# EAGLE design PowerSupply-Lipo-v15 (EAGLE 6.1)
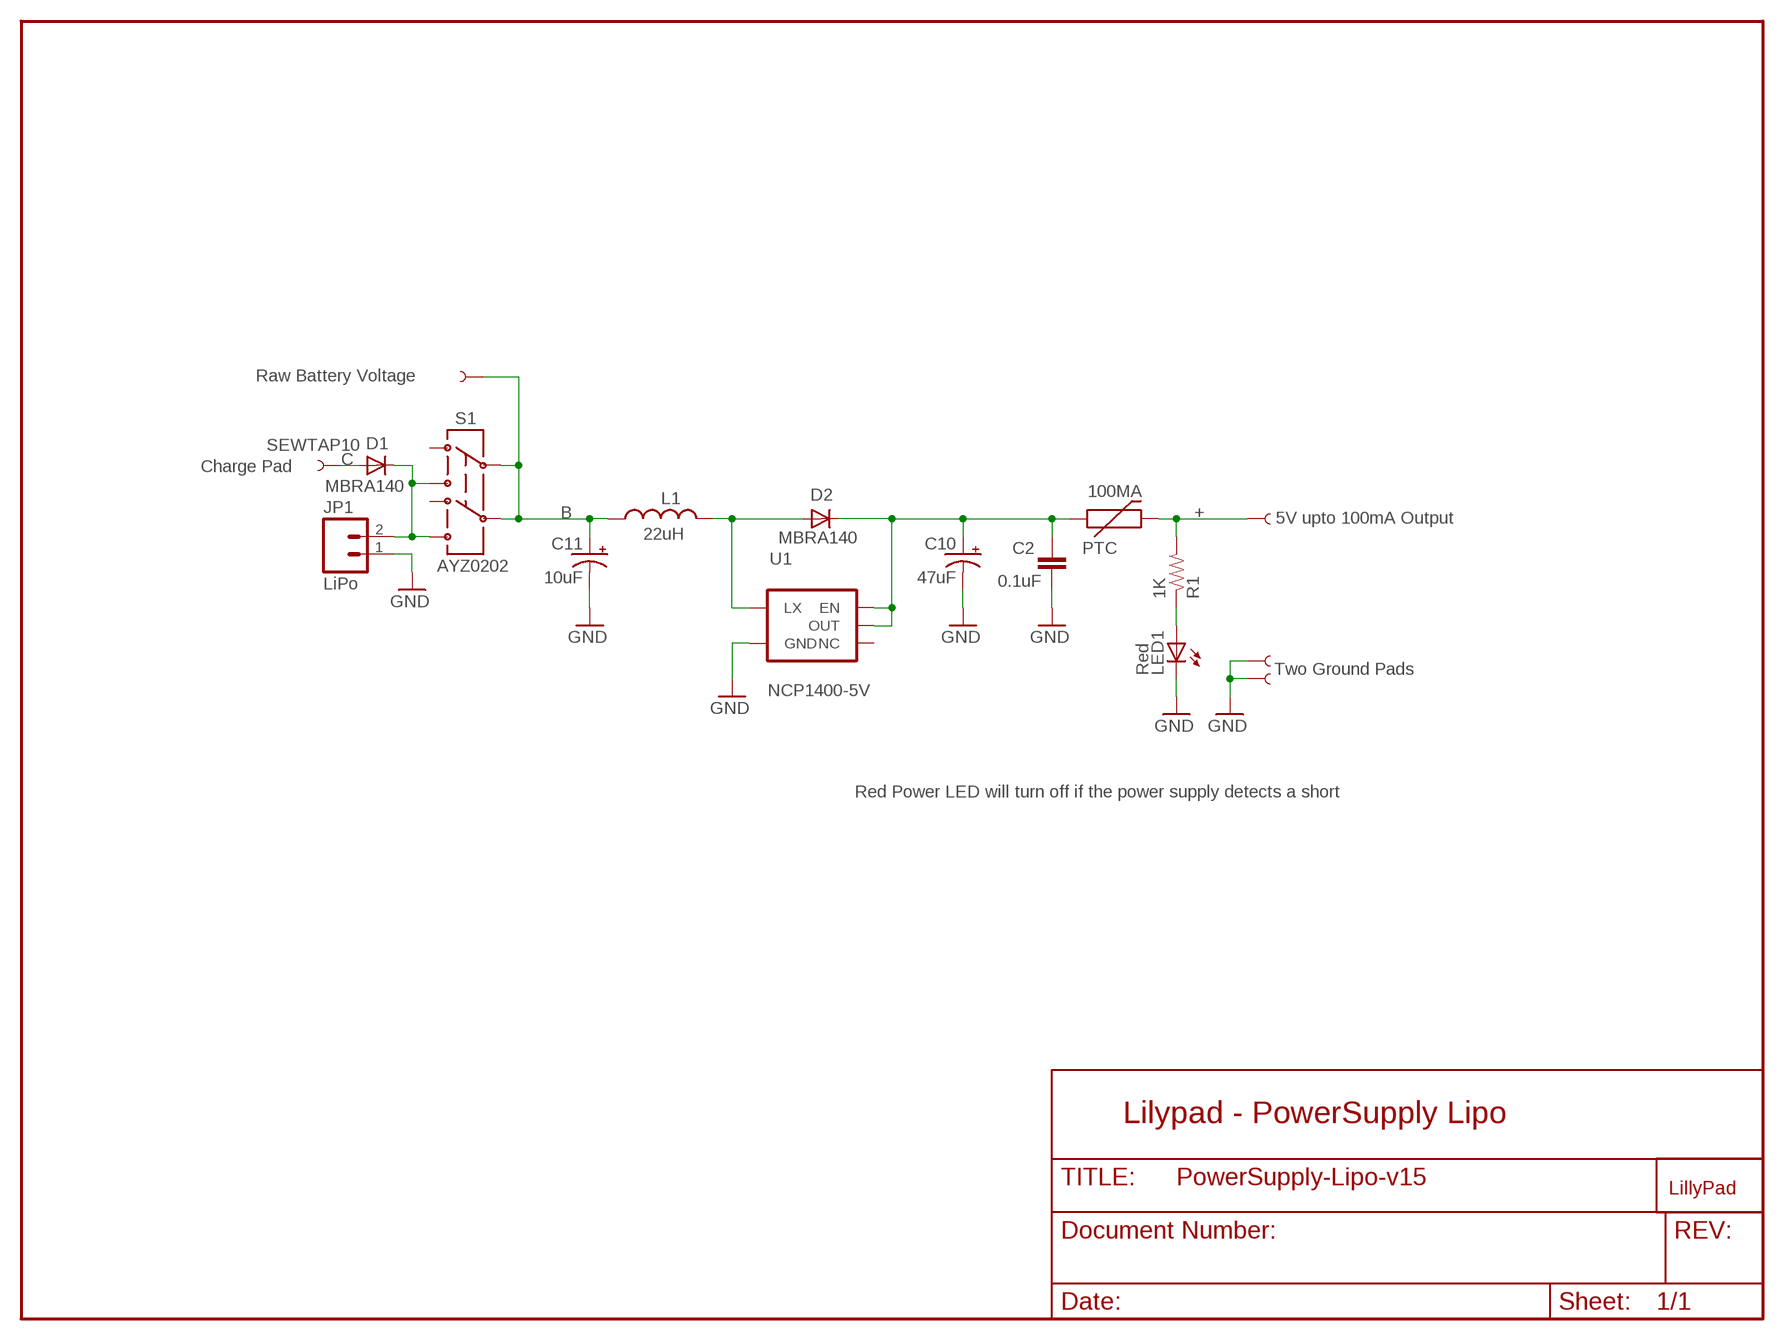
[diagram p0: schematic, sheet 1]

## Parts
100MA  PTC  PTCSMD  [PTC-1206]
C2  0.1uF  CAP0603-CAP  [0603-CAP]
C10  47uF  CAP_POL2  [EIA3528-21]
C11  10uF  CAP_POL1206  [CPOL_1206]
D1  MBRA140  DIODESMA  [SMA-DIODE]
D2  MBRA140  DIODESMA  [SMA-DIODE]
JP1  LiPo  M02-JST-2MM-SMT  [JST-2-SMD]
L1  22uH  INDUCTORCR54  [CR54]
LED1  Red  LED1206  [LED-1206]
R1  1K  RESISTOR0603-RES  [0603-RES]
S1  AYZ0202  [AYZ0202]
U1  NCP1400-5V  V_REG_NCP1400SOT23-5  [SOT23-5]
U$1  SEWTAP10  [PETAL-LONG-2-2SIDE]
U$2  SEWTAP10  [PETAL-LONG-2-2SIDE]
U$3  SEWTAP10  [PETAL-LONG-2-2SIDE]
U$4  SEWTAP10  [PETAL-LONG-2-2SIDE]
U$5  SEWTAP10  [PETAL-LONG-2-2SIDE]
U$7  LOGO-LPLP  [LOGO-LILYPAD]

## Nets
+: 100MA.2 R1.2 U$1.1
B: C11.A(+) L1.P$2 S1.2 S1.5 U$3.1
C: D1.A U$2.1
GND: C2.2 C10.C(-) C11.C(-) JP1.1 LED1.C U1.4(GND) U$4.1 U$5.1
N$1: LED1.A R1.1
N$2: 100MA.1 C2.1 C10.A(+) D2.C U1.1(EN) U1.2(OUT)
N$5: D1.C JP1.2 S1.1 S1.4
N$16: D2.A L1.P$1 U1.5(LX)
Unconnected: S1.3 S1.6 U1.3(NC)

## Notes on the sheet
- Raw Battery Voltage
- Charge Pad
- 5V upto 100mA Output
- Two Ground Pads
- Red Power LED will turn off if the power supply detects a short
- Lilypad - PowerSupply Lipo

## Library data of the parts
100MA = SparkFun:PTC: Resettable Fuse PTC
C2 = SparkFun:CAP: Capacitor
C10 C11 = SparkFun-Nate:CAP_POL
D1 D2 = SparkFun-Nate:DIODE
JP1 = SparkFun:M02: Header 2
L1 = SparkFun-Nate:INDUCTOR: Basic Inductor/Choke - 0603 and 1206
LED1 = SparkFun:LED: LEDs
R1 = SparkFun:RESISTOR: Resistor
S1 = SparkFun:AYZ0202: SPDT Slide Switch Simple SMD single-pull double-throw slide switch. Good for less than 350mA power switch, switching UARTs between devices, etc. Spark Fun Electronics SKU : COM-00597
U1 = SparkFun:V_REG_NCP1400: Switching step-up voltage regulator NCP1400 switiching regulator takes single cell AA and outputs 100mA at 3.3V or 5V with minimal number of external components.
U$1-U$5 = LilyPad-Wearables:SEWTAP
U$7 = LilyPad-Wearables:LOGO-LP

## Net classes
0 Default: width 0.203 mm
1 Power: width 0.305 mm
3 ButtonSignal: width 0.203 mm

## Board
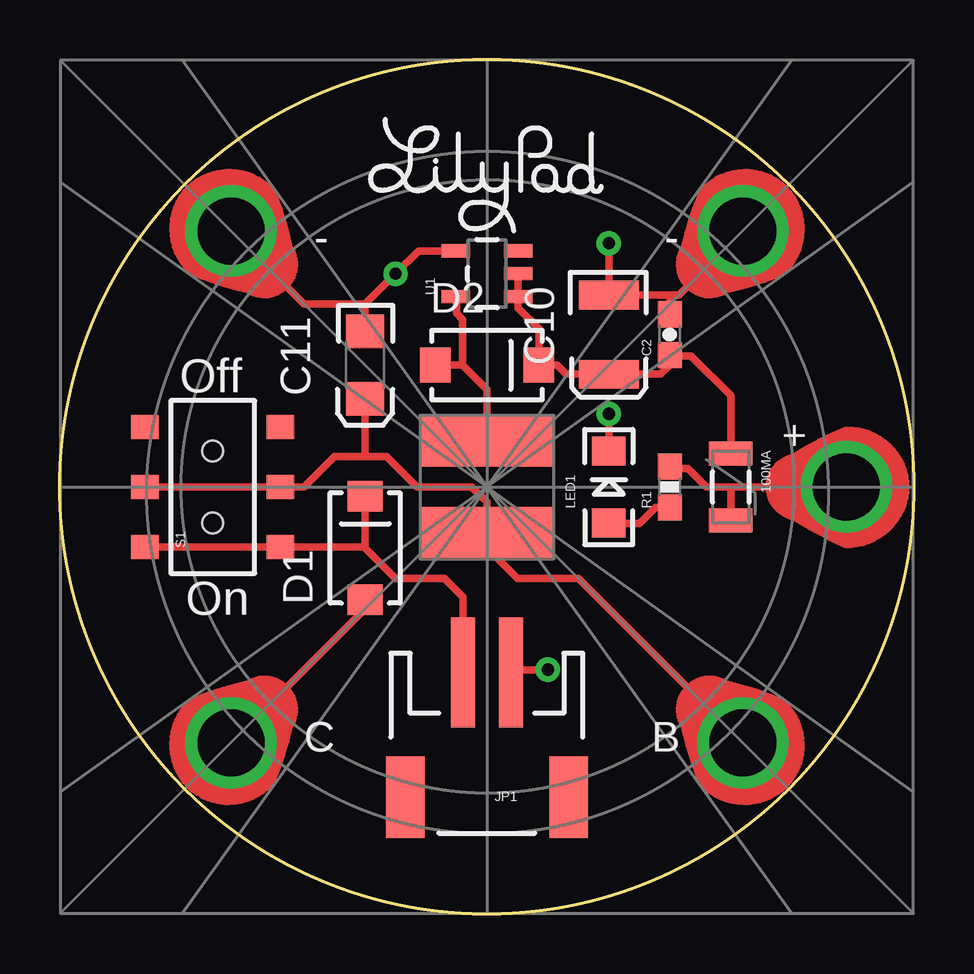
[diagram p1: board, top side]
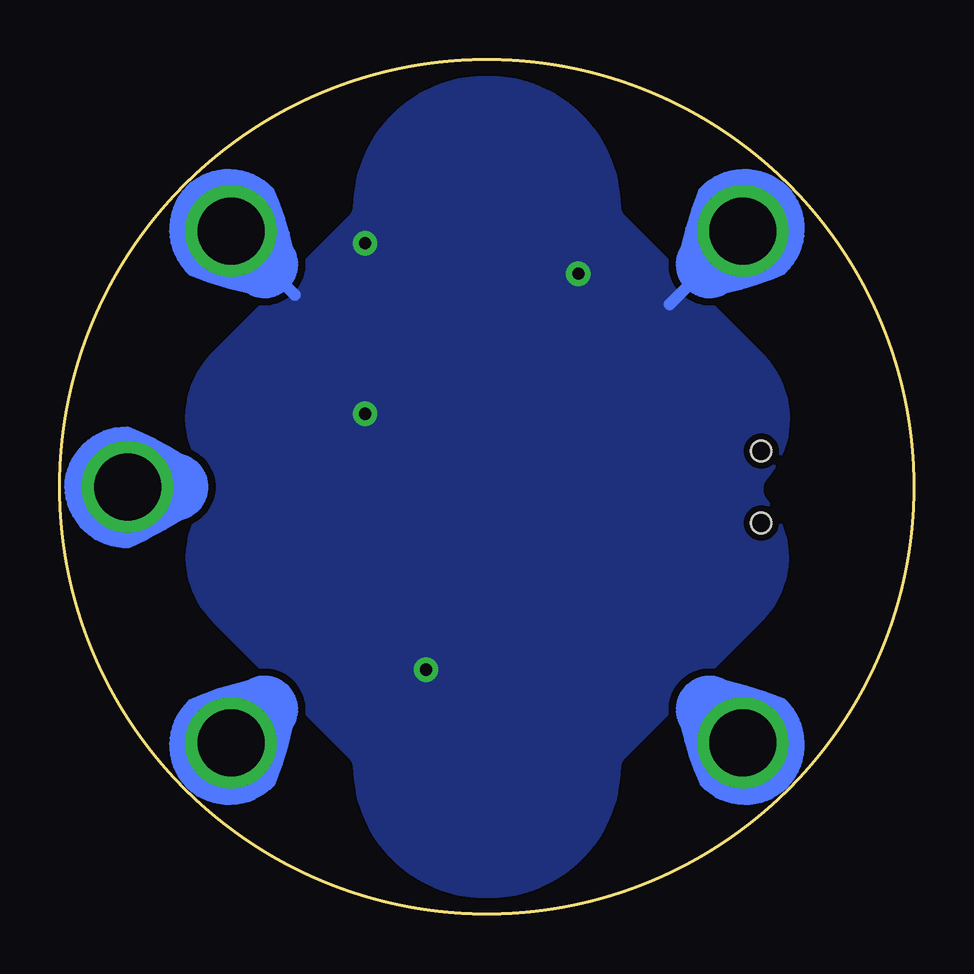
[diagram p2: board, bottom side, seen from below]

Size 35.6 x 35.6 mm. Coordinates in mm from the lower left corner, seen from the top.
Outline: circle at 17.8,17.8 radius 17.8
Copper layers (1*16): Top 0.035mm / dielectric 1.5mm / Bottom 0.035mm
Design rules "SparkFun": minimum track width 8mil, minimum drill 20mil, track to track 8mil, track to pad 8mil, pad to pad 8mil, via to via 8mil, smd to smd 8mil, copper to edge 10mil, drill to drill 8mil, minimum pad ring 12mil, minimum via ring 10mil, stop-mask expansion 4mil, vias tented up to drill 20mil, thermal gap 10mil
bRestrict: area 0,0 to 35.6,35.6

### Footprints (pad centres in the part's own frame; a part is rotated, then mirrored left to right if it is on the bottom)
PTC-1206 = smd 1 x 1.8: 1 -1.4,0; 2 1.4,0
0603-CAP = smd 1.1 x 1: 1 -0.85,0; 2 0.85,0
EIA3528-21 = smd 2.5 x 1.2: A 0,-1.65; C 0,1.65
CPOL_1206 = smd 1.6 x 1.4: A 0,-1.4; C 0,1.4
SMA-DIODE = smd 1.27 x 1.47: A -2.15,0; C 2.15,0
JST-2-SMD = smd 1 x 4.6: 1 -1,-3.7; 2 1,-3.7 | smd 1.6 x 3.4: NC1 -3.4,1.5; NC2 3.4,1.5
CR54 = smd 5.5 x 2.15: P$1 0,1.92; P$2 0,-1.92
LED-1206 = smd 1.2 x 1.4: A -1.5,0; C 1.5,0
0603-RES = smd 1.1 x 1: 1 -0.85,0; 2 0.85,0
AYZ0202 = smd 1 x 1.15: 1 -2.5,2.825; 2 0,2.825; 3 2.5,2.825; 4 -2.5,-2.825; 5 0,-2.825; 6 2.5,-2.825 | hole 0.85: 1.5,0; -1.5,0
SOT23-5 = smd 0.55 x 1.2: 1 -0.95,-1.3; 2 0,-1.3; 3 0.95,-1.3; 4 0.95,1.3; 5 -0.95,1.3
PETAL-LONG-2-2SIDE = drill 2.794 round: 1 0,0

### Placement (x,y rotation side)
100MA  27.96,17.8 270 top
C2  25.42,24.15 90 top
C10  22.88,24.15 0 top
C11  12.72,22.88 0 top
D1  12.72,15.26 90 top
D2  17.8,22.88 0 top
JP1  17.8,6.37 180 top
L1  17.8,17.8 0 top
LED1  22.88,17.8 90 top
R1  25.42,17.8 90 top
S1  6.37,17.8 90 top
U1  17.8,26.69 90 top
U$1  32.79,17.8 90 top
U$2  7.13,7.13 315 top
U$3  28.47,7.13 45 top
U$4  28.47,28.47 135 top
U$5  7.13,28.47 225 top
U$7  17.8,31.13 0 top

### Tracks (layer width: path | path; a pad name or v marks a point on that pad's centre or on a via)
+
  Top 0.305: 27.96,17.8 26.94,17.8 26.18,18.56 25.55,18.56 25.46,18.65 R1.2 | 27.96,17.8 U$1.1 | 27.96,17.8 100MA.2
B
  Top 0.305: 17.8,16.4 17.8,15.89 | 17.8,16.4 17.8,16.53 | 12.72,19.07 C11.A | 18.05,16.28 L1.P$2 17.8,15.89 | S1.2 S1.5 10.18,17.8 11.45,19.07 12.72,19.07 | 12.72,19.07 13.61,19.07 14.88,17.8 17.16,17.8 17.8,17.16 17.8,16.4 | U$3.1 21.61,13.99 19.07,13.99 17.8,15.26 17.8,15.89
C
  Top 0.305: D1.A 12.72,12.72 U$2.1
GND  (via drill 0.51)
  Top 0.305: C2.2 25.42,25.8 | 25.42,25.8 25.29,25.8 C10.C v22.88,27.96 | LED1.C v22.88,20.85 | 18.82,10.43 JP1.1 18.91,10.18 v20.34,10.18 | 12.72,24.15 C11.C 12.72,25.42 | U1.4 14.94,27.64 v13.99,26.69 12.72,25.42 | 12.72,25.42 10.18,25.42 8.91,26.69 | U$4.1 25.8,25.8 25.42,25.8
  Bottom 0.508: U$5.1 10.18,25.42 | U$4.1 25.8,25.8
  pour Bottom (isolate 0.305): 35.58,0.02 0.02,0.02 -0.23,15.26 -0.23,20.59 0.02,35.58 35.58,35.58
N$1
  Top 0.305: R1.1 24.82,16.95 24.15,16.28 22.88,16.28 LED1.A
N$2
  Top 0.305: U1.2 19.1,25.83 19.07,25.8 19.1,25.77 U1.1 19.1,25.26 19.96,24.4 D2.C 20.72,22.88 21.1,22.5 C10.A 25.04,22.5 25.42,22.88 25.42,23.26 | 100MA.1 27.96,21.61 26.31,23.26 25.42,23.26 | 25.42,23.26 C2.1
N$5
  Top 0.305: 12.72,17.8 D1.C 12.72,15.26 | 12.72,15.26 13.99,13.99 16.02,13.99 16.8,13.21 JP1.2 | 12.72,15.26 12.68,15.3 S1.4 3.62,15.3 3.58,15.26 S1.1
N$16
  Top 0.305: L1.P$1 17.8,21.86 16.78,22.88 | 16.78,22.88 16.78,24.79 16.53,25.04 16.53,25.67 16.5,25.7 U1.5 | 16.78,22.88 D2.A

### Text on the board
tPlace: - | - | Off | + | On | C | B
tValues: 22uH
